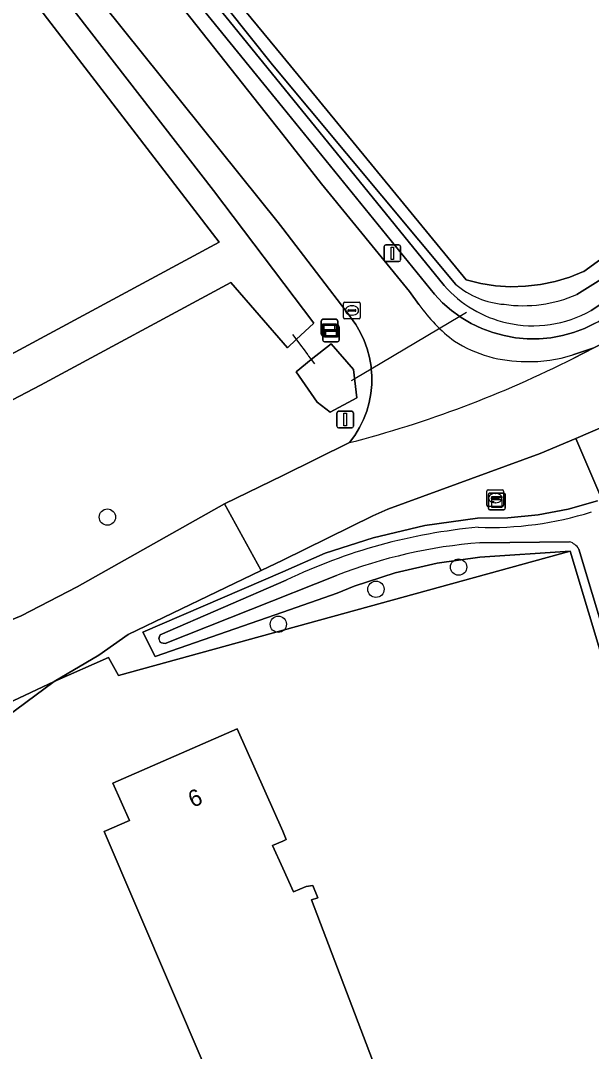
# Model space of a CAD drawing. Extents: x 161385 to 162589, y 388479 to 389756.
# Drawn here: x 162484.3 to 162518.5, y 389564.4 to 389626.2 of the extents above; entities that cross this region are included whole.
import ezdxf

# ---------------------------------------------------------------- set-up
doc = ezdxf.new("R2010")
doc.units = 0
for name, color, linetype in [('IMGEO_Boom', 7, 'Continuous'), ('IMGEO_Bouwland', 7, 'Continuous'), ('IMGEO_Brandkraan', 7, 'Continuous'), ('IMGEO_Duiker', 7, 'Continuous'), ('IMGEO_Erf', 7, 'Continuous'), ('IMGEO_Groenvoorziening', 7, 'Continuous'), ('IMGEO_Kast', 7, 'Continuous'), ('IMGEO_Lichtmast', 7, 'Continuous'), ('IMGEO_Oever', 7, 'Continuous'), ('IMGEO_Pand', 7, 'Continuous'), ('IMGEO_Pand_nummerreeks', 7, 'Continuous'), ('IMGEO_Rijbaan_lokaal_gesloten', 7, 'Continuous'), ('IMGEO_Rijbaan_lokaal_open', 7, 'Continuous'), ('IMGEO_Rioolput', 7, 'Continuous'), ('IMGEO_Verkeersbordpaal', 7, 'Continuous'), ('IMGEO_Verklikker', 7, 'Continuous'), ('IMGEO_Voetpad_open', 7, 'Continuous'), ('IMGEO_Waterloop', 7, 'Continuous')]:
    doc.layers.add(name, color=color, linetype=linetype)

msp = doc.modelspace()

# ---------------------------------------------------------------- linework, layer by layer
at = {"layer": 'IMGEO_Boom'}
for centre in [(162489.483, 389596.41), (162510.55, 389593.41), (162505.592, 389592.083), (162499.737, 389589.986)]:
    msp.add_circle(centre, 0.489, dxfattribs=at)
at = {"layer": 'IMGEO_Bouwland'}
for points in [[(162496.188, 389612.908), (162481.084, 389632.533), (162456.218, 389661.773), (162455.163, 389662.824), (162449.463, 389669.131), (162445.046, 389674.921), (162440.477, 389682.073), (162436.565, 389689.605), (162431.134, 389699.419), (162430.289, 389698.256), (162425.822, 389693.872), (162416.695, 389686.291), (162405.965, 389676.814), (162402.254, 389673.341), (162397.699, 389669.056), (162385.151, 389658.374), (162325.076, 389605.287), (162324.138, 389604.458), (162322.109, 389602.672), (162322.802, 389597.697), (162339.419, 389588.001), (162346.948, 389583.607), (162347.945, 389566.196), (162352.647, 389567.29)], [(162489.578, 389636.693), (162500, 389624.024), (162511.007, 389610.643), (162511.882, 389610.425), (162512.773, 389610.287), (162513.673, 389610.228), (162514.574, 389610.25), (162515.47, 389610.353), (162516.353, 389610.535), (162517.216, 389610.795), (162518.053, 389611.132), (162518.071, 389611.14), (162525.26, 389616.35), (162535.579, 389622.671), (162546.422, 389628.045)], [(162480.118, 389604.237), (162496.188, 389612.908)]]:
    msp.add_lwpolyline(points, dxfattribs=at)
at = {"layer": 'IMGEO_Brandkraan'}
for p, q in [((162503.653, 389608.378), (162503.653, 389609.23)), ((162503.728, 389609.304), (162504.58, 389609.304)), ((162503.955, 389608.847), (162504.353, 389608.847)), ((162504.141, 389609.084), (162504.166, 389609.084)), ((162504.654, 389609.23), (162504.654, 389608.378)), ((162504.58, 389608.304), (162503.728, 389608.304)), ((162503.912, 389608.798), (162503.912, 389608.81)), ((162504.35, 389608.761), (162503.952, 389608.761)), ((162504.164, 389608.524), (162504.139, 389608.524)), ((162504.396, 389608.81), (162504.396, 389608.798))]:
    msp.add_line(p, q, dxfattribs=at)
for points in [[(162503.653, 389608.378), (162503.653, 389609.23)], [(162503.728, 389609.304), (162504.58, 389609.304)], [(162504.654, 389609.23), (162504.654, 389608.378)], [(162504.58, 389608.304), (162503.728, 389608.304)]]:
    msp.add_lwpolyline(points, dxfattribs=at)
for centre, radius, start, end in [((162503.73, 389609.228), 0.0765, 91.55205, 178.44795), ((162503.73, 389609.228), 0.0765, 91.55205, 178.44795), ((162503.952, 389608.807), 0.0403, 85.87752, 175.75265), ((162504.357, 389608.809), 0.0386, 1.73085, 96.63898), ((162504.578, 389609.228), 0.0765, 1.55205, 88.44795), ((162504.578, 389609.228), 0.0765, 1.55205, 88.44795), ((162503.73, 389608.38), 0.0765, 181.55205, 268.44795), ((162503.73, 389608.38), 0.0765, 181.55205, 268.44795), ((162503.949, 389608.797), 0.0366, 178.93798, 274.71019), ((162504.353, 389608.804), 0.043, 264.86636, 352.45326), ((162504.578, 389608.38), 0.0765, 271.55205, 358.44795), ((162504.578, 389608.38), 0.0765, 271.55205, 358.44795)]:
    msp.add_arc(centre, radius, start, end, dxfattribs=at)
for centre, major_axis, ratio, start_param, end_param in [((162504.14, 389608.804), (-0.387, 0.002), 0.722429, 4.712389, 7.853982), ((162504.165, 389608.804), (-0.39, 0.002), 0.717154, 1.570796, 4.712389)]:
    msp.add_ellipse(centre, major_axis=major_axis, ratio=ratio, start_param=start_param, end_param=end_param, dxfattribs=at)
at = {"layer": 'IMGEO_Duiker'}
for points in [[(162511.026, 389608.69), (162510.617, 389608.447), (162509.979, 389608.067), (162505.315, 389605.29), (162504.421, 389604.757), (162504.116, 389604.576)], [(162500.595, 389607.36), (162501.146, 389606.618), (162501.201, 389606.543), (162501.223, 389606.514), (162501.485, 389606.161), (162501.499, 389606.143), (162501.554, 389606.068), (162501.647, 389605.943), (162501.907, 389605.593)]]:
    msp.add_lwpolyline(points, dxfattribs=at)
at = {"layer": 'IMGEO_Erf'}
msp.add_lwpolyline([(162530.551, 389561.722), (162522.858, 389575.675), (162517.235, 389594.37), (162490.14, 389586.904), (162489.546, 389587.986), (162486.294, 389586.559), (162482.871, 389584.036)], dxfattribs=at)
msp.add_lwpolyline([(162489.287, 389577.554), (162490.812, 389578.214), (162489.806, 389580.447), (162497.277, 389583.713), (162500, 389577.568), (162500.217, 389577.078), (162500, 389576.982), (162499.378, 389576.707), (162500, 389575.362), (162500.655, 389573.945), (162501.417, 389574.255), (162501.817, 389574.322), (162502.112, 389573.572), (162501.735, 389573.462), (162507.803, 389557.479), (162500, 389554.371), (162499.328, 389554.103)], close=True, dxfattribs=at)
at = {"layer": 'IMGEO_Groenvoorziening'}
for points in [[(162460.381, 389668.927), (162471.962, 389655.135), (162487.536, 389635.155), (162500, 389619.349), (162502.332, 389616.392), (162507.599, 389609.947), (162508.175, 389609.158)], [(162457.733, 389662.99), (162482.436, 389633.29), (162495.856, 389615.998), (162501.859, 389608.049), (162500.817, 389607.061), (162500.283, 389606.554), (162496.893, 389610.475), (162485.48, 389604.317), (162481.249, 389602.123)], [(162518.748, 389608.035), (162518.113, 389607.73), (162517.453, 389607.483), (162516.774, 389607.295), (162516.08, 389607.169), (162515.379, 389607.106), (162514.674, 389607.105), (162513.972, 389607.167), (162513.278, 389607.292), (162512.598, 389607.479), (162511.938, 389607.725), (162511.302, 389608.029), (162510.697, 389608.389), (162510.617, 389608.447), (162510.125, 389608.801), (162509.593, 389609.263), (162509.104, 389609.771), (162500, 389620.974), (162488.254, 389635.427)], [(162480.499, 389588.94), (162484.301, 389590.498), (162487.678, 389592.234), (162496.502, 389597.202), (162500, 389598.915), (162504.009, 389600.878), (162504.33, 389601.314), (162504.61, 389601.778), (162504.848, 389602.264), (162505.041, 389602.77), (162505.189, 389603.291), (162505.289, 389603.823), (162505.342, 389604.362), (162505.346, 389604.904), (162505.315, 389605.29), (162505.302, 389605.443), (162505.209, 389605.977), (162505.07, 389606.5), (162504.884, 389607.009), (162504.653, 389607.499), (162504.38, 389607.967), (162504.066, 389608.408), (162504.042, 389608.438), (162500, 389613.714), (162499.723, 389614.076), (162484.593, 389632.945)], [(162517.4, 389606.137), (162518.658, 389606.555), (162521.27, 389607.875), (162532.951, 389615.044), (162533.406, 389616.19), (162536.498, 389618.212), (162537.25, 389618.115), (162538.761, 389618.657)], [(162519.138, 389597.477), (162517.589, 389601.132), (162515.441, 389600.222), (162506.297, 389596.882), (162505.406, 389596.487), (162500, 389593.836), (162498.712, 389593.205), (162490.738, 389589.364), (162488.966, 389588.132), (162486.294, 389586.559), (162489.546, 389587.986), (162490.14, 389586.904), (162517.235, 389594.37), (162511.822, 389594.01), (162509.264, 389593.654), (162506.749, 389593.071), (162504.295, 389592.265), (162503.274, 389591.856), (162500, 389590.716), (162492.351, 389588.053), (162491.61, 389589.502), (162500, 389593.133), (162502.557, 389594.24), (162505.421, 389595.177), (162508.524, 389595.901), (162511.679, 389596.344), (162513.51, 389596.363), (162515.332, 389596.545), (162517.131, 389596.889), (162518.891, 389597.393)], [(162424.269, 389577.081), (162436.272, 389578.206), (162445.153, 389579.039), (162445.161, 389578.419), (162445.163, 389577.384), (162452.935, 389578.888), (162455.974, 389579.287), (162450.89, 389579.281), (162450.789, 389580.832), (162469.453, 389581.059), (162480.039, 389582.45), (162482.871, 389584.036), (162486.294, 389586.559), (162483.492, 389585.232), (162480.582, 389584.16), (162477.589, 389583.352), (162474.535, 389582.815), (162466.407, 389582.224), (162437.665, 389582.372), (162436.345, 389582.328), (162428.651, 389581.666)]]:
    msp.add_lwpolyline(points, dxfattribs=at)
msp.add_lwpolyline([(162500.799, 389605.13), (162501.71, 389605.858), (162502.899, 389606.807), (162504.244, 389605.272), (162504.443, 389603.561), (162502.856, 389602.704), (162502.062, 389603.302)], close=True, dxfattribs=at)
for centre, radius, start, end in [((162515.884, 389614.512), 9.386, 214.78193, 233.49202), ((162514.493, 389613.551), 7.805, 237.50831, 270.7595), ((162514.92, 389613.691), 7.95, 267.66256, 288.17404)]:
    msp.add_arc(centre, radius, start, end, dxfattribs=at)
at = {"layer": 'IMGEO_Kast'}
for p, q in [((162512.344, 389596.928), (162512.344, 389597.769)), ((162512.344, 389597.769), (162512.344, 389596.928)), ((162512.419, 389597.853), (162513.26, 389597.853)), ((162513.26, 389597.853), (162512.419, 389597.853)), ((162513.344, 389597.778), (162513.344, 389596.937)), ((162513.344, 389596.937), (162513.344, 389597.778)), ((162513.269, 389596.853), (162512.428, 389596.853)), ((162512.428, 389596.853), (162513.269, 389596.853))]:
    msp.add_line(p, q, dxfattribs=at)
for points in [[(162512.539, 389597.643), (162513.139, 389597.643), (162513.139, 389597.558), (162512.539, 389597.558), (162512.539, 389597.643)], [(162512.539, 389597.468), (162513.139, 389597.468), (162513.139, 389596.979), (162512.539, 389596.979), (162512.539, 389597.468)]]:
    msp.add_lwpolyline(points, dxfattribs=at)
msp.add_circle((162512.623, 389597.317), 0.0377, dxfattribs=at)
for centre, start, end in [((162512.422, 389597.775), 92.4484, 184.28452), ((162512.422, 389597.775), 92.4484, 184.28452), ((162513.266, 389597.775), 2.4484, 94.28452), ((162513.266, 389597.775), 2.4484, 94.28452), ((162512.422, 389596.931), 182.4484, 274.28452), ((162512.422, 389596.931), 182.4484, 274.28452), ((162513.266, 389596.931), 272.4484, 4.28452), ((162513.266, 389596.931), 272.4484, 4.28452)]:
    msp.add_arc(centre, 0.0779, start, end, dxfattribs=at)
at = {"layer": 'IMGEO_Lichtmast'}
for p, q in [((162503.251, 389601.86), (162503.251, 389602.66)), ((162503.251, 389602.66), (162503.251, 389601.86)), ((162503.351, 389602.76), (162504.141, 389602.76)), ((162504.141, 389602.76), (162503.351, 389602.76)), ((162504.241, 389602.66), (162504.241, 389601.86)), ((162504.241, 389601.86), (162504.241, 389602.66)), ((162504.141, 389601.76), (162503.351, 389601.76)), ((162503.351, 389601.76), (162504.141, 389601.76))]:
    msp.add_line(p, q, dxfattribs=at)
msp.add_lwpolyline([(162503.671, 389602.635), (162503.821, 389602.635), (162503.821, 389601.885), (162503.671, 389601.885), (162503.671, 389602.635)], dxfattribs=at)
for centre, start, end in [((162503.351, 389602.66), 90, 180), ((162503.351, 389602.66), 90, 180), ((162504.141, 389602.66), 0, 90), ((162504.141, 389602.66), 360, 90), ((162503.351, 389601.86), 180, 270), ((162503.351, 389601.86), 180, 270), ((162504.141, 389601.86), 270, 0), ((162504.141, 389601.86), 270, 0)]:
    msp.add_arc(centre, 0.1, start, end, dxfattribs=at)
at = {"layer": 'IMGEO_Oever'}
for points in [[(162459.319, 389673.752), (162499.393, 389623.525), (162510.388, 389610.356)], [(162546.422, 389628.045), (162535.579, 389622.671), (162525.26, 389616.35), (162518.071, 389611.14), (162518.053, 389611.132), (162517.216, 389610.795), (162516.353, 389610.535), (162515.47, 389610.353), (162514.574, 389610.25), (162513.673, 389610.228), (162512.773, 389610.287), (162511.882, 389610.425), (162511.007, 389610.643), (162500, 389624.024), (162489.578, 389636.693)], [(162488.254, 389635.427), (162500, 389620.974), (162509.104, 389609.771), (162509.593, 389609.263), (162510.125, 389608.801), (162510.617, 389608.447), (162510.697, 389608.389), (162511.302, 389608.029), (162511.938, 389607.725), (162512.598, 389607.479), (162513.278, 389607.292), (162513.972, 389607.167), (162514.674, 389607.105), (162515.379, 389607.106), (162516.08, 389607.169), (162516.774, 389607.295), (162517.453, 389607.483), (162518.113, 389607.73), (162518.748, 389608.035), (162518.902, 389608.12), (162532.116, 389616.803)], [(162509.693, 389610.292), (162500.61, 389621.47), (162488.867, 389635.919)], [(162517.644, 389609.766), (162523.986, 389613.721), (162535.683, 389621.595), (162546.472, 389627.155)], [(162547.281, 389625.877), (162541.357, 389623.228), (162535.288, 389619.834), (162531.684, 389617.46), (162518.496, 389608.794)], [(162518.891, 389597.393), (162517.131, 389596.889), (162515.332, 389596.545), (162513.51, 389596.363), (162511.679, 389596.344), (162508.524, 389595.901), (162505.421, 389595.177), (162502.557, 389594.24), (162500, 389593.133), (162491.61, 389589.502), (162492.351, 389588.053), (162500, 389590.716), (162503.274, 389591.856), (162504.295, 389592.265), (162506.749, 389593.071), (162509.264, 389593.654), (162511.822, 389594.01), (162517.235, 389594.37), (162522.858, 389575.675)], [(162517.207, 389594.936), (162511.831, 389594.872)], [(162553.023, 389524.065), (162552.828, 389524.145), (162552.749, 389524.207), (162552.626, 389524.387), (162552.561, 389524.538), (162552.495, 389524.762), (162552.373, 389525.281), (162550.517, 389532.219), (162548.715, 389536.979), (162547.511, 389539.233), (162544.866, 389543.113), (162541.214, 389547.515), (162539.939, 389549.052), (162539.671, 389549.407), (162537.114, 389553.154), (162531.013, 389562.008), (162523.361, 389575.887), (162517.765, 389594.494)], [(162503.226, 389592.903), (162492.953, 389588.838), (162492.831, 389588.849), (162492.721, 389588.876)], [(162492.571, 389589.12), (162492.601, 389589.257), (162492.649, 389589.36), (162500.216, 389592.635)]]:
    msp.add_lwpolyline(points, dxfattribs=at)
for centre, radius, start, end in [((162515.029, 389614.995), 7.113, 221.38854, 257.18737), ((162513.65, 389614.195), 5.037, 229.64508, 265.77818), ((162514.431, 389617.027), 7.94, 261.65708, 293.8674), ((162515.018, 389614.989), 7.105, 257.26971, 299.3116), ((162512.441, 389616.046), 20.258, 267.96159, 287.45513), ((162514.844, 389561.968), 33.977, 95.27472, 115.5), ((162514.167, 389564.875), 30.088, 94.45309, 111.32403), ((162516.864, 389593.929), 1.064, 32.07076, 71.16272), ((162492.835, 389589.114), 0.264, 178.79752, 244.36507)]:
    msp.add_arc(centre, radius, start, end, dxfattribs=at)
at = {"layer": 'IMGEO_Pand'}
msp.add_lwpolyline([(162499.328, 389554.103), (162500, 389554.371), (162507.803, 389557.479), (162501.735, 389573.462), (162502.112, 389573.572), (162501.817, 389574.322), (162501.417, 389574.255), (162500.655, 389573.945), (162500, 389575.362), (162499.378, 389576.707), (162500, 389576.982), (162500.217, 389577.078), (162500, 389577.568), (162497.277, 389583.713), (162489.806, 389580.447), (162490.812, 389578.214), (162489.287, 389577.554)], close=True, dxfattribs=at)
at = {"layer": 'IMGEO_Rijbaan_lokaal_gesloten'}
for points in [[(162508.175, 389609.158), (162507.599, 389609.947), (162502.332, 389616.392), (162500, 389619.349), (162487.536, 389635.155), (162471.962, 389655.135), (162460.381, 389668.927)], [(162457.368, 389666.342), (162468.15, 389652.663), (162484.593, 389632.945), (162499.723, 389614.076), (162500, 389613.714), (162504.042, 389608.438), (162504.066, 389608.408), (162504.38, 389607.967), (162504.653, 389607.499), (162504.884, 389607.009), (162505.07, 389606.5), (162505.209, 389605.977), (162505.302, 389605.443), (162505.315, 389605.29), (162505.346, 389604.904), (162505.342, 389604.362), (162505.289, 389603.823), (162505.189, 389603.291), (162505.041, 389602.77), (162504.848, 389602.264), (162504.61, 389601.778), (162504.33, 389601.314), (162504.009, 389600.878)], [(162517.458, 389605.949), (162518.658, 389606.555), (162517.4, 389606.137)], [(162483.492, 389585.232), (162486.294, 389586.559), (162488.966, 389588.132), (162490.738, 389589.364), (162498.712, 389593.205), (162496.502, 389597.202), (162487.678, 389592.234), (162484.301, 389590.498), (162480.499, 389588.94)]]:
    msp.add_lwpolyline(points, dxfattribs=at)
for centre, radius, start, end in [((162515.884, 389614.512), 9.386, 214.78193, 233.49202), ((162514.493, 389613.551), 7.805, 237.50831, 270.7595), ((162487.359, 389665.406), 66.642, 284.46834, 296.84997), ((162514.92, 389613.691), 7.95, 267.66256, 288.17404)]:
    msp.add_arc(centre, radius, start, end, dxfattribs=at)
at = {"layer": 'IMGEO_Rijbaan_lokaal_open'}
for points in [[(162538.761, 389618.657), (162532.951, 389615.044), (162521.27, 389607.875), (162518.658, 389606.555), (162517.458, 389605.949)], [(162504.009, 389600.878), (162500, 389598.915), (162496.502, 389597.202), (162498.712, 389593.205), (162500, 389593.836), (162505.406, 389596.487), (162506.297, 389596.882), (162515.441, 389600.222), (162517.589, 389601.132), (162519.486, 389601.936), (162520.856, 389602.637), (162521.889, 389603.165), (162532.625, 389609.608)]]:
    msp.add_lwpolyline(points, dxfattribs=at)
msp.add_arc((162487.359, 389665.406), 66.642, 284.46834, 296.84997, dxfattribs=at)
at = {"layer": 'IMGEO_Rioolput'}
for p, q in [((162512.251, 389597.124), (162512.251, 389597.976)), ((162512.326, 389598.05), (162513.178, 389598.05)), ((162512.739, 389597.83), (162512.764, 389597.83)), ((162513.252, 389597.976), (162513.252, 389597.124)), ((162512.51, 389597.544), (162512.51, 389597.556)), ((162512.948, 389597.507), (162512.55, 389597.507)), ((162512.553, 389597.593), (162512.951, 389597.593)), ((162512.762, 389597.27), (162512.737, 389597.27)), ((162512.994, 389597.556), (162512.994, 389597.544)), ((162513.178, 389597.05), (162512.326, 389597.05))]:
    msp.add_line(p, q, dxfattribs=at)
for points in [[(162512.251, 389597.124), (162512.251, 389597.976)], [(162512.326, 389598.05), (162513.178, 389598.05)], [(162513.252, 389597.976), (162513.252, 389597.124)], [(162513.178, 389597.05), (162512.326, 389597.05)]]:
    msp.add_lwpolyline(points, dxfattribs=at)
for centre, radius, start, end in [((162512.328, 389597.974), 0.0765, 91.55205, 178.44795), ((162512.328, 389597.974), 0.0765, 91.55205, 178.44795), ((162513.176, 389597.974), 0.0765, 1.55205, 88.44795), ((162513.176, 389597.974), 0.0765, 1.55205, 88.44795), ((162512.328, 389597.126), 0.0765, 181.55205, 268.44795), ((162512.328, 389597.126), 0.0765, 181.55205, 268.44795), ((162512.55, 389597.553), 0.0403, 85.87752, 175.75265), ((162512.547, 389597.543), 0.0366, 178.93798, 274.71019), ((162512.951, 389597.55), 0.043, 264.86636, 352.45326), ((162512.955, 389597.555), 0.0386, 1.73085, 96.63898), ((162513.176, 389597.126), 0.0765, 271.55205, 358.44795), ((162513.176, 389597.126), 0.0765, 271.55205, 358.44795)]:
    msp.add_arc(centre, radius, start, end, dxfattribs=at)
for centre, major_axis, ratio, start_param, end_param in [((162512.738, 389597.55), (-0.387, 0.002), 0.722429, 4.712389, 7.853982), ((162512.763, 389597.55), (-0.39, 0.002), 0.717154, 1.570796, 4.712389)]:
    msp.add_ellipse(centre, major_axis=major_axis, ratio=ratio, start_param=start_param, end_param=end_param, dxfattribs=at)
at = {"layer": 'IMGEO_Verkeersbordpaal'}
for p, q in [((162506.086, 389611.833), (162506.086, 389612.633)), ((162506.086, 389612.633), (162506.086, 389611.833)), ((162506.186, 389612.733), (162506.976, 389612.733)), ((162506.976, 389612.733), (162506.186, 389612.733)), ((162507.076, 389612.633), (162507.076, 389611.833)), ((162507.076, 389611.833), (162507.076, 389612.633)), ((162506.976, 389611.733), (162506.186, 389611.733)), ((162506.186, 389611.733), (162506.976, 389611.733))]:
    msp.add_line(p, q, dxfattribs=at)
msp.add_lwpolyline([(162506.506, 389612.608), (162506.656, 389612.608), (162506.656, 389611.858), (162506.506, 389611.858), (162506.506, 389612.608)], dxfattribs=at)
for centre, start, end in [((162506.186, 389612.633), 90, 180), ((162506.186, 389612.633), 90, 180), ((162506.976, 389612.633), 0, 90), ((162506.976, 389612.633), 360, 90), ((162506.186, 389611.833), 180, 270), ((162506.186, 389611.833), 180, 270), ((162506.976, 389611.833), 270, 0), ((162506.976, 389611.833), 270, 0)]:
    msp.add_arc(centre, 0.1, start, end, dxfattribs=at)
at = {"layer": 'IMGEO_Verklikker'}
for p, q in [((162502.409, 389608.276), (162503.199, 389608.276)), ((162503.199, 389608.276), (162502.409, 389608.276)), ((162502.309, 389607.376), (162502.309, 389608.176)), ((162502.309, 389608.176), (162502.309, 389607.376)), ((162502.401, 389607.024), (162502.401, 389607.824)), ((162502.401, 389607.824), (162502.401, 389607.024)), ((162502.501, 389607.924), (162503.291, 389607.924)), ((162503.291, 389607.924), (162502.501, 389607.924)), ((162503.299, 389608.176), (162503.299, 389607.376)), ((162503.299, 389607.376), (162503.299, 389608.176)), ((162503.391, 389607.824), (162503.391, 389607.024)), ((162503.391, 389607.024), (162503.391, 389607.824)), ((162503.199, 389607.276), (162502.409, 389607.276)), ((162502.409, 389607.276), (162503.199, 389607.276)), ((162503.291, 389606.924), (162502.501, 389606.924)), ((162502.501, 389606.924), (162503.291, 389606.924))]:
    msp.add_line(p, q, dxfattribs=at)
for points in [[(162502.41, 389608.008), (162503.198, 389608.008), (162503.198, 389607.544), (162502.41, 389607.544), (162502.41, 389608.008)], [(162502.475, 389607.943), (162502.475, 389607.609), (162503.133, 389607.609), (162503.133, 389607.943), (162502.475, 389607.943)], [(162502.502, 389607.656), (162503.29, 389607.656), (162503.29, 389607.192), (162502.502, 389607.192), (162502.502, 389607.656)], [(162502.567, 389607.591), (162502.567, 389607.257), (162503.225, 389607.257), (162503.225, 389607.591), (162502.567, 389607.591)]]:
    msp.add_lwpolyline(points, dxfattribs=at)
for centre, start, end in [((162502.409, 389608.176), 90, 180), ((162502.409, 389608.176), 90, 180), ((162503.199, 389608.176), 0, 90), ((162503.199, 389608.176), 360, 90), ((162502.501, 389607.824), 90, 180), ((162502.501, 389607.824), 90, 180), ((162503.291, 389607.824), 0, 90), ((162503.291, 389607.824), 360, 90), ((162502.409, 389607.376), 180, 270), ((162502.409, 389607.376), 180, 270), ((162502.501, 389607.024), 180, 270), ((162502.501, 389607.024), 180, 270), ((162503.199, 389607.376), 270, 0), ((162503.199, 389607.376), 270, 0), ((162503.291, 389607.024), 270, 0), ((162503.291, 389607.024), 270, 0)]:
    msp.add_arc(centre, 0.1, start, end, dxfattribs=at)
at = {"layer": 'IMGEO_Voetpad_open'}
msp.add_lwpolyline([(162522.166, 389600.076), (162520.856, 389602.637), (162519.486, 389601.936), (162517.589, 389601.132), (162519.138, 389597.477), (162519.465, 389596.546), (162519.885, 389595.351), (162523.628, 389597.829), (162522.929, 389598.903)], close=True, dxfattribs=at)
at = {"layer": 'IMGEO_Waterloop'}
for points in [[(162437.988, 389690.29), (162437.268, 389689.944), (162436.565, 389689.605), (162440.477, 389682.073), (162445.046, 389674.921), (162449.463, 389669.131), (162455.163, 389662.824), (162456.218, 389661.773), (162481.084, 389632.533), (162496.188, 389612.908), (162480.118, 389604.237)], [(162510.388, 389610.356), (162499.393, 389623.525), (162459.319, 389673.752)], [(162481.249, 389602.123), (162485.48, 389604.317), (162496.893, 389610.475), (162500.283, 389606.554), (162500.817, 389607.061), (162501.859, 389608.049), (162495.856, 389615.998), (162482.436, 389633.29), (162457.733, 389662.99)], [(162488.867, 389635.919), (162500.61, 389621.47), (162509.693, 389610.292)], [(162546.472, 389627.155), (162535.683, 389621.595), (162523.986, 389613.721), (162517.644, 389609.766)], [(162518.496, 389608.794), (162531.684, 389617.46), (162535.288, 389619.834), (162541.357, 389623.228), (162547.281, 389625.877)], [(162511.831, 389594.872), (162517.207, 389594.936)], [(162517.765, 389594.494), (162523.361, 389575.887), (162531.013, 389562.008), (162537.114, 389553.154), (162539.671, 389549.407), (162539.939, 389549.052), (162541.214, 389547.515), (162544.866, 389543.113), (162547.511, 389539.233), (162548.715, 389536.979), (162550.517, 389532.219), (162552.373, 389525.281), (162552.495, 389524.762), (162552.561, 389524.538), (162552.626, 389524.387), (162552.749, 389524.207), (162552.828, 389524.145), (162553.023, 389524.065)], [(162492.721, 389588.876), (162492.831, 389588.849), (162492.953, 389588.838), (162503.226, 389592.903)], [(162500.216, 389592.635), (162492.649, 389589.36), (162492.601, 389589.257), (162492.571, 389589.12)]]:
    msp.add_lwpolyline(points, dxfattribs=at)
msp.add_lwpolyline([(162500.799, 389605.13), (162502.062, 389603.302), (162502.856, 389602.704), (162504.443, 389603.561), (162504.244, 389605.272), (162502.899, 389606.807), (162501.71, 389605.858)], close=True, dxfattribs=at)
for centre, radius, start, end in [((162515.029, 389614.995), 7.113, 221.38854, 257.18737), ((162513.65, 389614.195), 5.037, 229.64508, 265.77818), ((162514.431, 389617.027), 7.94, 261.65708, 293.8674), ((162515.018, 389614.989), 7.105, 257.26971, 299.3116), ((162512.441, 389616.046), 20.258, 267.96159, 287.45513), ((162514.844, 389561.968), 33.977, 95.27472, 115.5), ((162514.167, 389564.875), 30.088, 94.45309, 111.32403), ((162516.864, 389593.929), 1.064, 32.07076, 71.16272), ((162492.835, 389589.114), 0.264, 178.79752, 244.36507)]:
    msp.add_arc(centre, radius, start, end, dxfattribs=at)

# ---------------------------------------------------------------- texts
at = {"layer": 'IMGEO_Pand_nummerreeks'}
msp.add_text('6', height=1, rotation=23.61288, dxfattribs=at).set_placement((162494.603, 389578.965))

doc.saveas('drawing.dxf')
